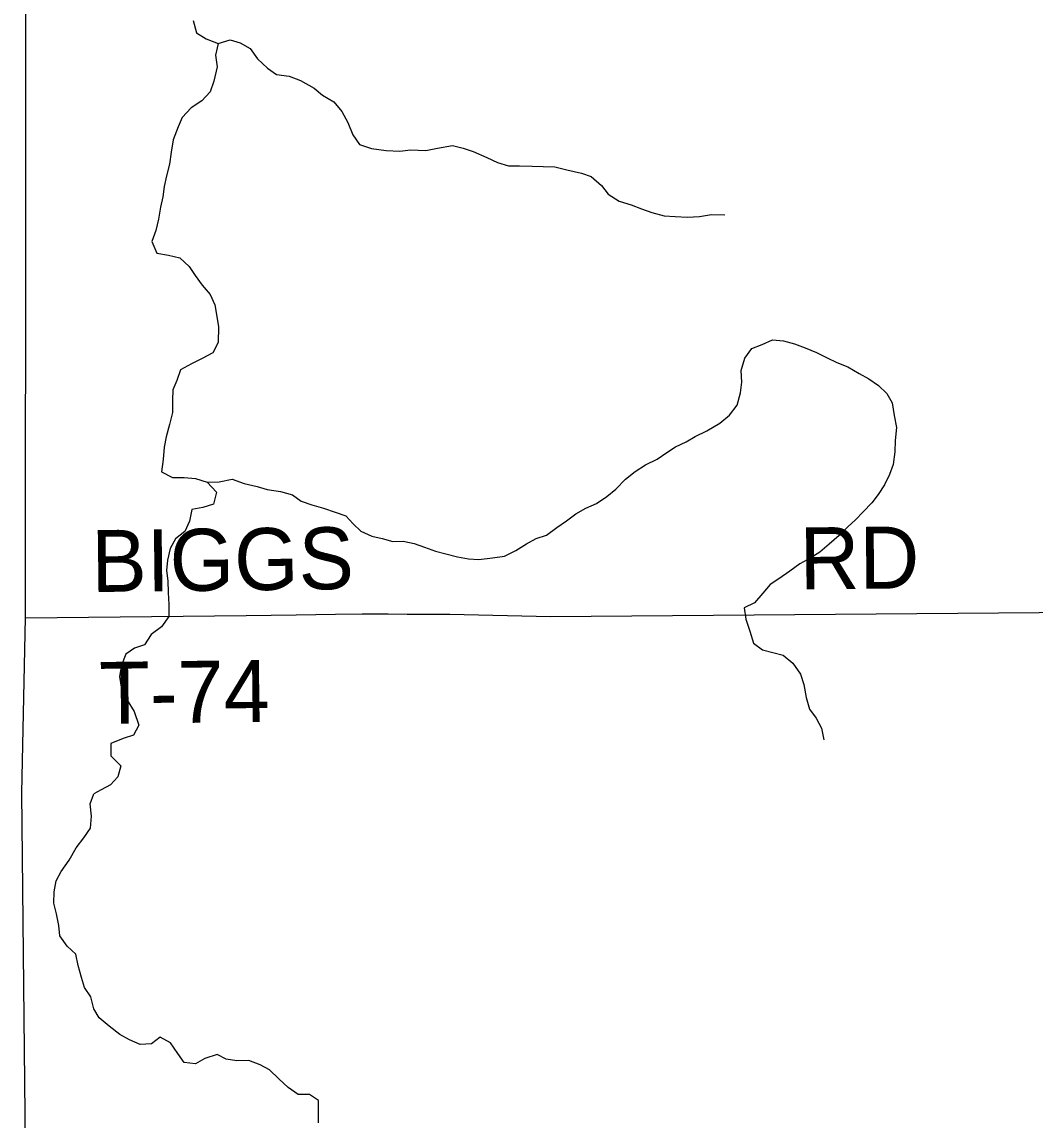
# Model space of a CAD drawing. Extents: x 1857828 to 2277390, y 930619 to 1324581.
# Drawn here: x 2062648 to 2067552, y 1182554 to 1187870 of the extents above; entities that cross this region are included whole.
import ezdxf

# ---------------------------------------------------------------- set-up
doc = ezdxf.new("R2010")
doc.units = 0
for name, color, linetype in [('GM_X_County_Road', 7, 'Continuous'), ('GM_X_Minor_River', 7, 'Continuous'), ('GM_X_Township_Road', 7, 'Continuous'), ('GM_X_Township_Road_Text', 7, 'Continuous')]:
    doc.layers.add(name, color=color, linetype=linetype)

msp = doc.modelspace()

# ---------------------------------------------------------------- linework, layer by layer
at = {"layer": 'GM_X_County_Road'}
msp.add_lwpolyline([(2062695.9, 1179474.1), (2062647.5, 1184138.4), (2062664.4, 1184984.3), (2062667.8, 1189321.7), (2062743.6, 1193118)], dxfattribs=at)
at = {"layer": 'GM_X_Minor_River'}
for points in [[(2063475.8, 1187877.1), (2063491.9, 1187817), (2063540, 1187789), (2063598, 1187765), (2063656, 1187783.2), (2063704.1, 1187769.2), (2063752.1, 1187741.2), (2063788.2, 1187691.1), (2063836.3, 1187647.1), (2063880.4, 1187615.1), (2063940.4, 1187607.1), (2063996.5, 1187587.2), (2064062.6, 1187549.2), (2064102.7, 1187515.1), (2064156.8, 1187483.1), (2064196.9, 1187437.1), (2064225, 1187383), (2064249.1, 1187322.9), (2064281.2, 1187276.8), (2064339.3, 1187256.9), (2064411.3, 1187246.9), (2064477.3, 1187245), (2064529.3, 1187251.1), (2064603.3, 1187247.2), (2064659.3, 1187259.3), (2064731.3, 1187271.4), (2064783.3, 1187259.5), (2064831.4, 1187243.5), (2064897.5, 1187213.5), (2064949.5, 1187189.5), (2065003.6, 1187173.6), (2065055.6, 1187173.7), (2065117.6, 1187171.7), (2065171.6, 1187169.8), (2065227.6, 1187167.9), (2065285.6, 1187153.9), (2065355.7, 1187138), (2065403.7, 1187122), (2065453.8, 1187078), (2065485.9, 1187035.9), (2065538, 1187001.9), (2065596.1, 1186983.9), (2065646.1, 1186966), (2065696.2, 1186948), (2065756.2, 1186932.1), (2065810.2, 1186928.1), (2065870.2, 1186924.2), (2065928.2, 1186928.3), (2065986.2, 1186938.4), (2066050.2, 1186936.5)], [(2063598, 1187765), (2063584.2, 1187708.9), (2063592.3, 1187652.8), (2063576.5, 1187582.6), (2063558.6, 1187532.4), (2063518.7, 1187488.3), (2063466.7, 1187454.1), (2063422.8, 1187407.9), (2063403, 1187361.8), (2063379.1, 1187299.6), (2063369.2, 1187239.5), (2063361.4, 1187181.3), (2063347.5, 1187125.2), (2063335.6, 1187073), (2063329.7, 1187022.9), (2063317.8, 1186972.8), (2063308, 1186914.6), (2063296.1, 1186860.5), (2063276.2, 1186806.3), (2063300.3, 1186750.2), (2063356.4, 1186740.2), (2063412.4, 1186728.3), (2063456.5, 1186686.3), (2063486.6, 1186642.2), (2063520.7, 1186596.1), (2063558.8, 1186550.1), (2063581, 1186500), (2063591.1, 1186443.9), (2063599.2, 1186393.8), (2063597.4, 1186317.6), (2063571.5, 1186267.4), (2063519.5, 1186241.3), (2063467.6, 1186215.2), (2063415.7, 1186185), (2063397.8, 1186134.9), (2063377.9, 1186088.7), (2063376, 1186038.6), (2063376.1, 1185978.5), (2063362.3, 1185920.3), (2063346.4, 1185862.1), (2063336.5, 1185812), (2063330.6, 1185751.9), (2063322.8, 1185691.7), (2063376.9, 1185663.7), (2063432.9, 1185663.8), (2063486.9, 1185659.9), (2063544.9, 1185641.9), (2063589, 1185593.8), (2063575.2, 1185535.7), (2063523.2, 1185519.6), (2063469.2, 1185509.5), (2063459.3, 1185453.3), (2063435.5, 1185403.2), (2063391.5, 1185367), (2063365.6, 1185320.9), (2063351.8, 1185264.7), (2063347.9, 1185214.6), (2063354, 1185164.5), (2063356.1, 1185108.4), (2063358.3, 1185050.2), (2063358.4, 1184992.1), (2063322.5, 1184941.9), (2063272.6, 1184903.8), (2063240.7, 1184853.6), (2063192.7, 1184837.5), (2063150.8, 1184809.4), (2063128.9, 1184755.2), (2063119, 1184701.1), (2063129.2, 1184638.9), (2063157.3, 1184586.8), (2063191.4, 1184530.8), (2063213.6, 1184464.6), (2063187.7, 1184416.5), (2063137.7, 1184400.4), (2063077.8, 1184376.2), (2063077.9, 1184316.1), (2063126, 1184268), (2063112.2, 1184215.9), (2063076.2, 1184175.7), (2063030.3, 1184151.6), (2062994.8, 1184133.4)], [(2063544.9, 1185641.9), (2063602.9, 1185644), (2063664.9, 1185656.1), (2063723, 1185636.1), (2063787, 1185620.2), (2063835, 1185606.2), (2063899.1, 1185596.3), (2063957.1, 1185580.3), (2063999.2, 1185550.3), (2064051.2, 1185532.3), (2064107.3, 1185516.4), (2064163.3, 1185496.4), (2064215.4, 1185478.4), (2064251.5, 1185440.4), (2064287.5, 1185404.4), (2064341.6, 1185380.4), (2064391.6, 1185368.4), (2064443.7, 1185354.5), (2064493.7, 1185356.5), (2064545.7, 1185344.6), (2064595.8, 1185326.6), (2064649.8, 1185308.6), (2064699.8, 1185294.7), (2064755.9, 1185280.7), (2064809.9, 1185270.8), (2064859.9, 1185266.8), (2064925.9, 1185274.9), (2064983.9, 1185283), (2065037.8, 1185311.2), (2065089.8, 1185343.3), (2065137.7, 1185369.5), (2065187.7, 1185385.6), (2065237.6, 1185421.7), (2065283.5, 1185453.9), (2065329.5, 1185488), (2065377.4, 1185516.1), (2065429.4, 1185538.3), (2065479.3, 1185572.4), (2065523.2, 1185608.6), (2065569.1, 1185656.7), (2065617, 1185692.9), (2065667, 1185725.1), (2065722.9, 1185753.2), (2065768.8, 1185785.3), (2065810.8, 1185813.4), (2065862.7, 1185837.6), (2065906.7, 1185863.7), (2065962.6, 1185889.8), (2066026.5, 1185928), (2066072.4, 1185966.2), (2066110.3, 1186014.3), (2066126.2, 1186074.5), (2066132.1, 1186126.6), (2066130, 1186182.8), (2066147.8, 1186242.9), (2066181.7, 1186289.1), (2066231.7, 1186309.2), (2066281.6, 1186331.3), (2066333.6, 1186325.4), (2066387.7, 1186311.4), (2066439.7, 1186291.5), (2066493.8, 1186269.5), (2066545.9, 1186243.5), (2066591.9, 1186221.5), (2066646, 1186199.5), (2066700.1, 1186167.5), (2066748.1, 1186141.5), (2066794.2, 1186109.5), (2066834.3, 1186071.5), (2066860.4, 1186025.4), (2066870.5, 1185965.3), (2066880.7, 1185907.2), (2066874.8, 1185843), (2066872.9, 1185788.9), (2066865.1, 1185726.7), (2066847.2, 1185678.6), (2066823.3, 1185628.4), (2066793.4, 1185582.3), (2066761.5, 1185542.1), (2066719.6, 1185498), (2066683.7, 1185459.8), (2066645.7, 1185425.7), (2066603.8, 1185383.5), (2066555.9, 1185341.4), (2066510, 1185303.2), (2066466.1, 1185275.1), (2066414.1, 1185246.9), (2066364.2, 1185210.8), (2066312.3, 1185174.6), (2066270.3, 1185146.5), (2066234.4, 1185104.3), (2066194.5, 1185058.2), (2066144.6, 1185034.1), (2066152.7, 1184977.9), (2066170.9, 1184919.8), (2066189, 1184861.7), (2066233.1, 1184829.7), (2066283.1, 1184817.7), (2066333.1, 1184803.8), (2066379.2, 1184765.7), (2066417.4, 1184711.7)], [(2066417.4, 1184711.7), (2066433.5, 1184661.6), (2066443.6, 1184599.4), (2066459.7, 1184543.3), (2066491.9, 1184499.3), (2066518, 1184451.2), (2066530.1, 1184395.1)], [(2064082.5, 1182539.6), (2064083.9, 1182595.8), (2064083.3, 1182648), (2064038.8, 1182677.6), (2063984.5, 1182677.1), (2063935.9, 1182710.7), (2063891.2, 1182752.3), (2063846.5, 1182796), (2063800, 1182821.6), (2063745.5, 1182841.1), (2063687.2, 1182840.5), (2063636.9, 1182848), (2063592.4, 1182871.6), (2063532.4, 1182850.9), (2063488.4, 1182826.4), (2063432.1, 1182831.8), (2063401.4, 1182875.6), (2063366.7, 1182927.4), (2063316.1, 1182955), (2063274.3, 1182922.5), (2063220, 1182919.9), (2063167.5, 1182941.4), (2063121, 1182967), (2063070.3, 1183008.6), (2063021.6, 1183048.2), (2062995, 1183092.1), (2062980.3, 1183150.2), (2062949.6, 1183196), (2062935, 1183244), (2062920.3, 1183302), (2062907.6, 1183356.1), (2062867, 1183395.8), (2062830.3, 1183445.6), (2062825.7, 1183495.7), (2062815, 1183551.8), (2062802.4, 1183603.8), (2062803.8, 1183658), (2062813.2, 1183712.3), (2062836.8, 1183756.7), (2062876.4, 1183811.3), (2062909.9, 1183871.8), (2062947.6, 1183920.4), (2062979.2, 1183966.9), (2062984.6, 1184025.1), (2062977.9, 1184085.2), (2062995.4, 1184133.6)]]:
    msp.add_lwpolyline(points, dxfattribs=at)
at = {"layer": 'GM_X_Township_Road'}
msp.add_lwpolyline([(2062664.4, 1184984.3), (2063733.3, 1184997.1), (2063975, 1184999.1), (2064164.9, 1185002.7), (2064294.7, 1185003.7), (2064420.6, 1185004.8), (2064512.5, 1185003.5), (2064718.3, 1185003.2), (2065206, 1184991.2), (2067769.4, 1185012.3)], dxfattribs=at)

# ---------------------------------------------------------------- texts
at = {"layer": 'GM_X_Township_Road_Text'}
for s, rotation, p in [('BIGGS', 0.6871, (2062985.3, 1185109.6)), ('RD', 0.4955, (2066413.3, 1185122.8)), ('T-74', 0.7069, (2063023.9, 1184471))]:
    msp.add_text(s, height=300, rotation=rotation, dxfattribs=at).set_placement(p)

doc.saveas('drawing.dxf')
